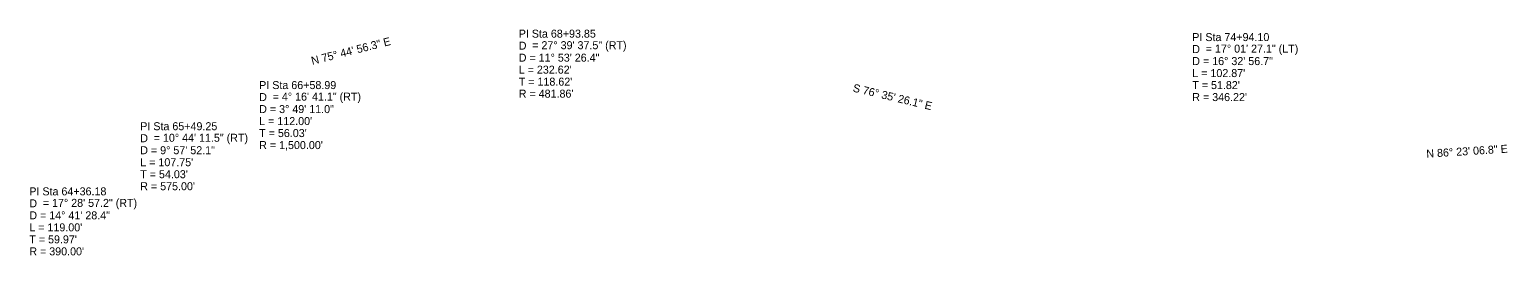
# Model space of a CAD drawing. Extents: x 928111 to 937215, y 683930 to 686530.
# Drawn here: x 932751 to 934044, y 684651 to 684849 of the extents above; entities that cross this region are included whole.
import ezdxf

# ---------------------------------------------------------------- set-up
doc = ezdxf.new("R2010")
doc.units = 0
doc.layers.add('Exist Horizontal Alignment Curve and Spiral Data', color=7, linetype='Continuous')
doc.layers.add('Exist Horizontal Alignment Direction Label', color=7, linetype='Continuous')

msp = doc.modelspace()

# ---------------------------------------------------------------- texts
at = {"layer": 'Exist Horizontal Alignment Curve and Spiral Data'}
for s, p in [('PI Sta 68+93.85', (933179, 684842)), ('PI Sta 74+94.10', (933768, 684839)), ('D', (933179, 684831.5)), ('= 27%%d 39\' 37.5" (RT)', (933190.8, 684831.9)), ('D', (933768, 684828.5)), ('= 17%%d 01\' 27.1" (LT)', (933779.8, 684828.9)), ('D = 11%%d 53\' 26.4"', (933179, 684821)), ("L = 232.62'", (933179, 684810.5)), ('D = 16%%d 32\' 56.7"', (933768, 684818)), ("T = 118.62'", (933179, 684800)), ("L = 102.87'", (933768, 684807.5)), ('PI Sta 66+58.99', (932952, 684797)), ('D', (932952, 684786.5)), ('= 4%%d 16\' 41.1" (RT)', (932963.8, 684786.9)), ("R = 481.86'", (933179, 684789.5)), ("T = 51.82'", (933768, 684797)), ("R = 346.22'", (933768, 684786.5)), ('D = 3%%d 49\' 11.0"', (932952, 684776)), ('PI Sta 65+49.25', (932848, 684761)), ("L = 112.00'", (932952, 684765.5)), ('D', (932848, 684750.5)), ('= 10%%d 44\' 11.5" (RT)', (932859.8, 684750.9)), ("T = 56.03'", (932952, 684755)), ('D = 9%%d 57\' 52.1"', (932848, 684740)), ("R = 1,500.00'", (932952, 684744.5)), ("L = 107.75'", (932848, 684729.5)), ("T = 54.03'", (932848, 684719)), ("R = 575.00'", (932848, 684708.5)), ('PI Sta 64+36.18', (932751, 684704)), ('= 17%%d 28\' 57.2" (RT)', (932762.8, 684693.9)), ('D', (932751, 684693.5)), ('D = 14%%d 41\' 28.4"', (932751, 684683)), ("L = 119.00'", (932751, 684672.5)), ("T = 59.97'", (932751, 684662)), ("R = 390.00'", (932751, 684651.5))]:
    msp.add_text(s, height=7, dxfattribs=at).set_placement(p)
at = {"layer": 'Exist Horizontal Alignment Direction Label'}
for s, rotation, p in [('N 75%%d 44\' 56.3" E', 14.251, (932998.5, 684818.2)), ('S 76%%d 35\' 26.1" E', 346.5906, (933470.7, 684794.9)), ('N 86%%d 23\' 06.8" E', 3.6148, (933972.9, 684736.9))]:
    msp.add_text(s, height=7, rotation=rotation, dxfattribs=at).set_placement(p)

doc.saveas('drawing.dxf')
